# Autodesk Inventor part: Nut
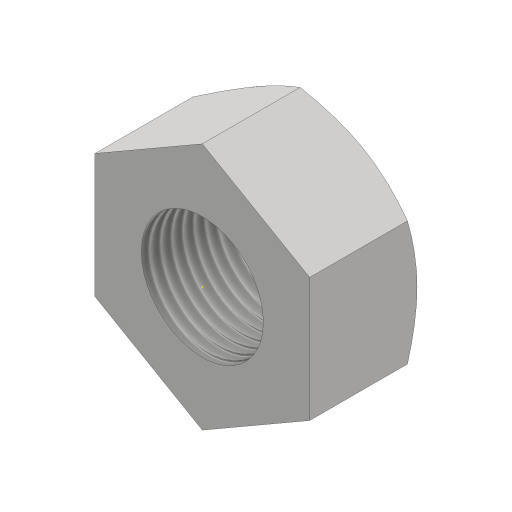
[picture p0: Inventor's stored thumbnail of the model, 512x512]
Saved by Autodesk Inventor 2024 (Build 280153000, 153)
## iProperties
Created: 2016-05
Part Number: Nut
Material: Generic
Document SubType Name: Modeling
Designer: CADCIM
Density: 1 g/cm^3
Appearance: Default
Author: CADCIM
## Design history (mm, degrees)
sketch "Sketch1"
  geometry: L1 (0, -33.255)-(-28.8, -16.628); L2 (-28.8, -16.628)-(-28.8, 16.628); L3 (-28.8, 16.628)-(0, 33.255); L4 (0, 33.255)-(28.8, 16.628); L5 (28.8, 16.628)-(28.8, -16.628); L6 (28.8, -16.628)-(0, -33.255); 2 further points
  constraints: 12 end point, 1 coincident, 13 other
  dimensions: "d0" = 57.6 distance between parallel lines of L2 L5
extrude "Extrusion1" new body sketch "Sketch1" stored distance "d1" = 28.8; taper "d2" = 0 deg
sketch "Sketch2"
  geometry: L1 (0, 33.255)-(-28.8, 16.628) reference; C1 r 28.8 at (0, 0); 1 further point
  constraints: 1 centre point, 1 coincident, 1 tangent
extrude "Extrusion2" sketch "Sketch2" distance "d3" = 28.8; taper "d4" = 60 deg
hole "Hole1" diameter "d7" = 32.752; stored, may be unused: countersink angle "d11" = 90 deg, drill point angle "d13" = 118 deg; dims "d5" = 10, "d6" = 10, "d8" = 72, "d9" = 4, "d10" = 2, "d12" = 85.1
body "Solid1"
sketch "Sketch3"
  geometry: 1 further point
